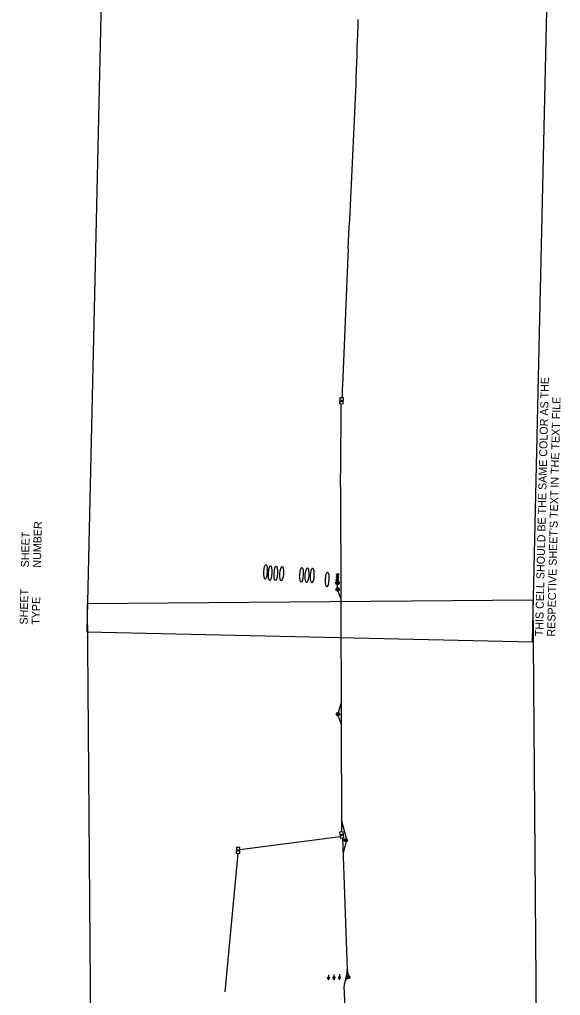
# Model space of a CAD drawing. Extents: x 601462 to 605493, y 331960 to 402715.
# Drawn here: x 603587 to 604770, y 340128 to 342262 of the extents above; entities that cross this region are included whole.
import ezdxf

# ---------------------------------------------------------------- set-up
doc = ezdxf.new("R2010")
doc.units = 0
for name, color, linetype in [('Default', 7, 'Continuous'), ('P_FTMS', 7, 'Continuous'), ('P_FTMSConduit', 7, 'Continuous'), ('P_MISC_TXT_2A (Construction)', 7, 'Continuous'), ('P_MISC_TXT_2B (Construction)', 7, 'Continuous')]:
    doc.layers.add(name, color=color, linetype=linetype)

# ---------------------------------------------------------------- blocks, each defined once
blk = doc.blocks.new('FTMS_FCV')
at = {"layer": 'P_FTMS'}
blk.add_line((13, 16), (1, -22), dxfattribs=at)
blk.add_lwpolyline([(39, 24), (-39, 24), (-39, -24), (39, -24)], close=True, dxfattribs=at)
blk.add_lwpolyline([(-12, 16), (1, -22)], dxfattribs=at)
blk = doc.blocks.new('FMD')
at = {"layer": 'P_FTMS'}
for p, q in [((17, 18), (-17, 18)), ((-16, 16), (-16, 18)), ((16, 16), (-16, 16)), ((-15, 15), (-15, 20)), ((15, 19), (-15, 19)), ((15, 15), (-15, 15)), ((14, 20), (-14, 20)), ((13, 22), (-13, 22)), ((-13, 13), (-13, 21)), ((13, 13), (-13, 13)), ((-12, 12), (-12, 23)), ((12, 12), (-12, 12)), ((11, 23), (-11, 23)), ((10, 25), (-10, 25)), ((-10, 10), (-10, 24)), ((10, 10), (-10, 10)), ((-9, 9), (-9, 26)), ((9, 9), (-9, 9)), ((8, 26), (-8, 26)), ((7, 28), (-7, 28)), ((-7, 7), (-7, 27)), ((7, 7), (-7, 7)), ((-6, 6), (-6, 29)), ((6, 6), (-6, 6)), ((5, 29), (-5, 29)), ((4, 31), (-4, 31)), ((-4, 4), (-4, 30)), ((4, 4), (-4, 4)), ((-3, 3), (-3, 32)), ((3, 3), (-3, 3)), ((2, 32), (-2, 32)), ((1, 34), (-1, 34)), ((-1, 1), (-1, 33)), ((1, 1), (-1, 1)), ((0, 0), (0, 34)), ((1, 1), (1, 33)), ((3, 3), (3, 32)), ((4, 4), (4, 30)), ((6, 6), (6, 29)), ((7, 7), (7, 27)), ((9, 9), (9, 26)), ((10, 10), (10, 24)), ((12, 12), (12, 23)), ((13, 13), (13, 21)), ((15, 15), (15, 20)), ((16, 16), (16, 18))]:
    blk.add_line(p, q, dxfattribs=at)
blk.add_lwpolyline([(-17, 17), (0, 34), (17, 17), (0, 0)], close=True, dxfattribs=at)
blk = doc.blocks.new('POINT_DISPLAY')
at = {"layer": 'Default'}
blk.add_line((0, 0), (0, 0), dxfattribs=at)
blk = doc.blocks.new('_U222')
at = {"layer": 'P_FTMS'}
for p, q in [((-4.5, 3.2), (1.5, -0.2)), ((-4.4, 2.8), (1.3, -0.4)), ((-4.3, 3.5), (1.8, 0)), ((-3.9, 3.4), (-4.3, 2.6)), ((-4.3, 2.4), (1, -0.6)), ((-3.5, 3.4), (-4.2, 2.2)), ((-4.2, 2), (0.7, -0.8)), ((-3.2, 3.3), (-4.1, 1.7)), ((-4.1, 1.6), (0.5, -1)), ((-2.9, 3.3), (-4, 1.3)), ((-4, 1.2), (0.2, -1.2)), ((-2.6, 3.2), (-3.9, 0.9)), ((-2.2, 3.2), (-3.8, 0.5)), ((-3.8, 0.7), (0, -1.4)), ((-1.9, 3.2), (-3.7, 0.1)), ((-3.7, 0.3), (-0.3, -1.6)), ((-3.5, 3.4), (2, 0.2)), ((-1.6, 3.1), (-3.5, -0.3)), ((-1.3, 3.1), (-3.4, -0.7)), ((-0.9, 3), (-3.3, -1.2)), ((-0.6, 3), (-3.2, -1.6)), ((-0.3, 2.9), (-3.1, -2)), ((0, 2.9), (-3, -2.4)), ((0.4, 2.8), (-2.9, -2.8)), ((-2.7, 3.3), (2.3, 0.4)), ((0.7, 2.8), (-2.7, -3.2)), ((1, 2.8), (-2.5, -3.4)), ((-1.9, 3.2), (2.5, 0.6)), ((1.3, 2.7), (-1.8, -2.9)), ((1.7, 2.7), (-1.2, -2.3)), ((-1.1, 3), (2.8, 0.8)), ((2, 2.6), (-0.5, -1.8)), ((-0.3, 2.9), (3.1, 1)), ((2.3, 2.6), (0.1, -1.3)), ((0.5, 2.8), (3.3, 1.2)), ((2.6, 2.5), (0.7, -0.8)), ((1.3, 2.7), (3.6, 1.4)), ((3, 2.5), (1.4, -0.3)), ((3.3, 2.4), (2, 0.2)), ((2.2, 2.6), (3.8, 1.6)), ((3.6, 2.4), (2.7, 0.7)), ((3, 2.5), (4.1, 1.8)), ((3.9, 2.3), (3.3, 1.2)), ((3.8, 2.4), (4.3, 2.1)), ((4.3, 2.3), (4, 1.7)), ((-3.6, -0.1), (-0.5, -1.8)), ((-3.5, -0.5), (-0.8, -2)), ((-3.4, -0.9), (-1.1, -2.2)), ((-3.3, -1.3), (-1.3, -2.4)), ((-3.2, -1.7), (-1.6, -2.7)), ((-3, -2.2), (-1.8, -2.9)), ((-2.9, -2.6), (-2.1, -3.1)), ((-2.8, -3), (-2.3, -3.3)), ((-2.7, -3.4), (-2.6, -3.5))]:
    blk.add_line(p, q, dxfattribs=at)
blk.add_lwpolyline([(-4.6, 3.5), (4.6, 2.3), (-2.7, -3.5)], close=True, dxfattribs=at)
blk.add_blockref('POINT_DISPLAY', (4.6, 2.3), dxfattribs=at)

msp = doc.modelspace()

# ---------------------------------------------------------------- linework, layer by layer
at = {"layer": 'P_FTMS'}
for p, q in [((604285, 341032.3), (604278.1, 341031.7)), ((604284.9, 341032.5), (604278.2, 341032)), ((604284.7, 341032.7), (604278.3, 341032.2)), ((604278.4, 341032.3), (604278.8, 341027.4)), ((604284.5, 341033), (604278.5, 341032.5)), ((604278.6, 341032.6), (604279, 341027.1)), ((604284.2, 341033.2), (604278.7, 341032.7)), ((604278.8, 341032.9), (604279.3, 341026.9)), ((604283.9, 341033.4), (604279, 341033)), ((604279, 341033.1), (604279.6, 341026.7)), ((604283.6, 341033.6), (604279.3, 341033.3)), ((604279.3, 341033.3), (604279.8, 341026.6)), ((604279.5, 341033.4), (604280.1, 341026.5)), ((604283.1, 341033.8), (604279.7, 341033.5)), ((604279.7, 341033.6), (604280.3, 341026.3)), ((604280, 341033.7), (604280.6, 341026.3)), ((604280.2, 341033.8), (604280.8, 341026.2)), ((604282.5, 341034), (604280.3, 341033.8)), ((604280.4, 341033.9), (604281.1, 341026.2)), ((604280.7, 341033.9), (604281.3, 341026.1)), ((604280.9, 341034), (604281.5, 341026.1)), ((604281.1, 341034), (604281.8, 341026.1)), ((604281.4, 341034.1), (604282, 341026.1)), ((604281.6, 341034.1), (604282.3, 341026.1)), ((604281.9, 341034.1), (604282.5, 341026.2)), ((604282.1, 341034.1), (604282.7, 341026.2)), ((604282.3, 341034), (604283, 341026.3)), ((604282.6, 341034), (604283.2, 341026.4)), ((604282.8, 341033.9), (604283.4, 341026.5)), ((604283.1, 341033.8), (604283.7, 341026.6)), ((604283.3, 341033.7), (604283.9, 341026.8)), ((604283.6, 341033.6), (604284.1, 341026.9)), ((604283.8, 341033.5), (604284.3, 341027.1)), ((604284.1, 341033.3), (604284.6, 341027.3)), ((604284.3, 341033.1), (604284.8, 341027.6)), ((604284.6, 341032.8), (604285, 341027.9)), ((604284.9, 341032.5), (604285.2, 341028.2)), ((604285.6, 341031.1), (604277.7, 341030.5)), ((604285.6, 341030.9), (604277.7, 341030.2)), ((604285.6, 341030.7), (604277.7, 341030)), ((604285.7, 341030.4), (604277.7, 341029.8)), ((604285.7, 341030.2), (604277.7, 341029.5)), ((604285.4, 341031.6), (604277.8, 341031)), ((604285.5, 341031.4), (604277.8, 341030.7)), ((604277.8, 341030.9), (604278, 341028.7)), ((604285.7, 341029.9), (604277.8, 341029.3)), ((604285.7, 341029.7), (604277.8, 341029.1)), ((604285.3, 341031.8), (604277.9, 341031.2)), ((604285.6, 341029.4), (604277.9, 341028.8)), ((604285.2, 341032.1), (604278, 341031.5)), ((604278, 341031.5), (604278.2, 341028.1)), ((604285.6, 341029.2), (604278, 341028.6)), ((604285.5, 341029), (604278.1, 341028.4)), ((604278.2, 341032), (604278.5, 341027.7)), ((604285.4, 341028.7), (604278.2, 341028.1)), ((604285.3, 341028.5), (604278.4, 341027.9)), ((604285.2, 341028.2), (604278.5, 341027.7)), ((604285.1, 341028), (604278.7, 341027.4)), ((604284.9, 341027.7), (604278.9, 341027.2)), ((604284.7, 341027.4), (604279.2, 341027)), ((604284.4, 341027.2), (604279.5, 341026.8)), ((604284.1, 341026.9), (604279.8, 341026.6)), ((604283.7, 341026.6), (604280.3, 341026.4)), ((604283.1, 341026.3), (604280.9, 341026.2)), ((604285.1, 341032.1), (604285.4, 341028.7)), ((604285.4, 341031.5), (604285.6, 341029.3)), ((604262.1, 340173.4), (604262.3, 340167.3)), ((604274, 340174), (604274.2, 340167.8)), ((604286, 340174.5), (604286.2, 340168.3))]:
    msp.add_line(p, q, dxfattribs=at)
for centre, radius in [((604281.7, 341030.1), 4), ((604282.3, 341015.7), 3.75), ((604283, 340743), 3.75), ((604299.8, 340467.6), 3.75), ((604305.4, 340168.1), 3.75)]:
    msp.add_circle(centre, radius, dxfattribs=at)
for centre, start, end in [((604281.9, 341020.2), 222.4831, 328.7387), ((604282.8, 341011.2), 42.4831, 148.7387), ((604282.6, 340747.4), 222.4831, 328.7387), ((604283.4, 340738.5), 42.4831, 148.7387), ((604299.4, 340472.1), 222.4831, 328.7387), ((604300.3, 340463.1), 42.4831, 148.7387), ((604304.5, 340163.7), 25.7548, 132.0104), ((604306.2, 340172.6), 205.7548, 312.0104)]:
    msp.add_arc(centre, 3.75, start, end, dxfattribs=at)
for centre in [(604124.5, 341054.3), (604134.6, 341051.7), (604147, 341051), (604159.8, 341050.3), (604203.3, 341047.5), (604215.3, 341046.8), (604226.7, 341046.1), (604259.4, 341037.4)]:
    msp.add_ellipse(centre, major_axis=(0.9, 16), ratio=0.23471, dxfattribs=at)
at = {"layer": 'P_FTMSConduit'}
for p, q in [((604305, 341761.4), (604292.7, 341461.7)), ((604288.5, 341241.2), (604291, 340485.6)), ((604281, 341019.5), (604282, 341026.1)), ((604282.4, 341011.8), (604289.2, 340995.6)), ((604284, 340746.6), (604289.6, 340767.4)), ((604283.4, 340738.5), (604289.7, 340720.9)), ((604301.3, 340471.1), (604290.9, 340511.8)), ((604287.7, 340475), (604068.6, 340446.7)), ((604292.6, 340472.9), (604303.3, 340184.1)), ((604300.3, 340463.1), (604294, 340438.8)), ((604064.1, 340438.7), (604035.5, 340135.8)), ((604303.3, 340184.1), (604304.9, 340171.9)), ((604302.6, 340177.2), (604297.6, 340157.3)), ((604301.7, 340165), (604302.2, 340165.7)), ((604305.8, 340171.9), (604306.1, 340174.9)), ((604298.6, 340100.4), (604296.5, 340148.6))]:
    msp.add_line(p, q, dxfattribs=at)
for centre, radius, start, end in [((586251.9, 342814.3), 18083.8, 356.66163, 358.24901), ((606985.6, 341365.1), 2694.7, 177.9429, 178.5234), ((592910.2, 341403.7), 11379.5, 359.18187, 0.09138), ((604278.3, 340183.2), 25, 346.0914, 2.1127), ((604321.5, 340149.7), 25, 142.2445, 182.4436)]:
    msp.add_arc(centre, radius, start, end, dxfattribs=at)
at = {"layer": 'P_MISC_TXT_2A (Construction)'}
msp.add_lwpolyline([(604708.5, 340900.9), (604744.2, 342475.5), (603769.4, 342497.6), (603733.8, 340923)], close=True, dxfattribs=at)
at = {"layer": 'P_MISC_TXT_2B (Construction)'}
msp.add_lwpolyline([(604722, 339417.2), (604709.6, 340992.1), (603734.6, 340984.5), (603747, 339409.5)], close=True, dxfattribs=at)

# ---------------------------------------------------------------- block references
at = {"layer": 'P_FTMS'}
for name, p, xscale, yscale, rotation in [('FTMS_FCV', (604290.6, 341428.2), 0.1640416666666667, 0.16404166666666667, 87.23689791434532), ('FMD', (604278.7, 341037.1), 0.16404166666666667, 0.1640416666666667, -93.36246654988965), ('FMD', (604279, 341042.7), 0.16404166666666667, 0.1640416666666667, -93.36246654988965), ('FMD', (604279.4, 341048.3), 0.16404166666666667, 0.1640416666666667, -93.36246654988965), ('FTMS_FCV', (604291.1, 340479.2), 0.1640416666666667, 0.16404166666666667, 99.05313895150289), ('FTMS_FCV', (604064.5, 340445.2), 0.16404166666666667, 0.16404166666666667, 88.04112391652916), ('_U222', (604261.7, 340165), 0.6330710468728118, 0.6330710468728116, -103.40702453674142), ('_U222', (604274.9, 340165.6), 0.6330710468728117, -0.6330710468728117, -72.75708063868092), ('_U222', (604286.9, 340166.1), 0.6330710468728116, -0.6330710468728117, -72.75708063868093)]:
    msp.add_blockref(name, p, dxfattribs=dict(at, xscale=xscale, yscale=yscale, rotation=rotation))

# ---------------------------------------------------------------- texts
at = {"layer": 'P_MISC_TXT_2A (Construction)'}
for s, p in [('THIS CELL SHOULD BE THE SAME COLOR AS THE', (604731.4, 340913.3)), ("RESPECTIVE SHEET'S TEXT IN THE TEXT FILE", (604757.7, 340912.7)), ('NUMBER', (603633.3, 341063.2)), ('SHEET', (603607.1, 341063.8)), ('SHEET', (603604.2, 340938.9)), ('TYPE', (603630.5, 340938.3))]:
    msp.add_text(s, height=17.5, rotation=88.7029, dxfattribs=at).set_placement(p)

doc.saveas('drawing.dxf')
